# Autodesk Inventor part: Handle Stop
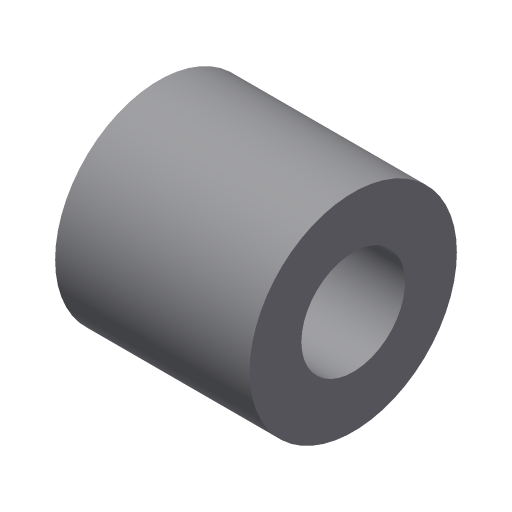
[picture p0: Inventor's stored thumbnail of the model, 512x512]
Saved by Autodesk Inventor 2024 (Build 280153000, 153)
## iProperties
Shininess: 77.0
Length Units: 11269
Angle Units: 11279
Time Units: 11290
Mass Units: 11283
Length Display Precision: 3
Angle Display Precision: 2
Compacted: True
Created: 2002-02
Part Number: Handle Stop
Document SubType Name: Modeling
Designer: ***
Density: 1 g/cm^3
Material: Generic
Appearance: Default
Density: 0.0
Volumn: 0.0
Area: 0.0
PropertySet Name: Model Information
Control State: 0
Master: False
Checked Out: False
Author: ***
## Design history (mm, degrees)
sketch "Sketch1"
  geometry: L1 (0, 0)-(0, -2); L2 (0, -2)-(8, -2); L3 (8, -2)-(8, 13); L4 (8, 13)-(4, 13); L5 (4, 13)-(4, 0); L6 (4, 0)-(0, 0)
  constraints: 12 end point, 4 parallel, 1 perpendicular, 1 vertical
  dimensions: "d0" = 16 diameter of L3 L1; "d1" = 8 diameter of L5 L1; "d2" = 2 distance of L1.start L1.end; "d3" = 15 distance of L2.end L3.end
revolve "Revolution1" sketch "Sketch1" stored, may be unused: angle "d4" = 90 deg
body "Solid1"
